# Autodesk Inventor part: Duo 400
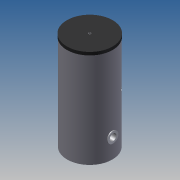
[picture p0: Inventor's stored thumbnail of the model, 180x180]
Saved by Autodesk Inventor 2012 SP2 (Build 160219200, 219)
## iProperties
Created: 2014-05
Part Number: Duo 400
Material: Default
Document SubType Name: Modeling
Designer: michel
Density: 1 g/cm^3
Author: michel
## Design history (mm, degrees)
sketch "Sketch1"
  geometry: C1 r 375 at (0, 0); 1 further point
  constraints: 1 centre point, 1 coincident
  dimensions: "d0" = 750 diameter of C1
extrude "Extrusion1" new body sketch "Sketch1" distance "d1" = 1630; taper "d2" = 0 deg
sketch "Sketch2"
  geometry: L1 (-375, 1630)-(375, 1630) reference; L2 (-375, 0)-(375, 0) reference; L3 (375, 0)-(375, 1630) reference; L4 (375, 1630)-(380, 1630); L5 (380, 1630)-(380, 1580); L6 (380, 1580)-(375, 1580); L7 (375, 1580)-(375, 1630); L8 (0, -326)-(0, 1956) reference; 1 further point
  constraints: 8 end point, 2 parallel, 1 horizontal, 1 perpendicular
  dimensions: "d3" = 5 distance of L5.end L6.end; "d4" = 50 distance of L4.end L5.end
revolve "Revolution1" sketch "Sketch2" stored, may be unused: angle "d5" = 90 deg
workplane "Work Plane1"
workplane "Work Plane2"
workplane "Work Plane3"
workplane "Work Plane4"
workplane "Work Plane5"
workplane "Work Plane6"
sketch "Sketch3"
  geometry: L1 (532, 1470)-(-532, 1470) reference; L2 (532, 870)-(-532, 870) reference; L3 (532, 770)-(-532, 770) reference; L4 (532, 330)-(-532, 330) reference; L5 (532, 70)-(-532, 70) reference; L6 (375, 0)-(375, 1580) reference; L7 (375, 70)-(335, 70); L8 (335, 70)-(335, 86.625); L9 (335, 86.625)-(375, 86.625); L10 (375, 86.625)-(375, 70); L11 (375, 330)-(335, 330); L12 (335, 330)-(335, 346.625); L13 (335, 346.625)-(375, 346.625); L14 (375, 346.625)-(375, 330); L15 (374.76, 770)-(334.76, 770); L16 (334.76, 770)-(334.76, 786.625); L17 (334.76, 786.625)-(374.76, 786.625); L18 (374.76, 786.625)-(374.76, 770); L19 (375, 1470)-(335, 1470); L20 (335, 1470)-(335, 1486.625); L21 (335, 1486.625)-(375, 1486.625); L22 (375, 1486.625)-(375, 1470); L23 (375, 870)-(335, 870); L24 (335, 870)-(335, 883.22); L25 (335, 883.22)-(375, 883.22); L26 (375, 883.22)-(375, 870); 1 further point
  constraints: 40 end point, 10 parallel, 5 horizontal, 5 perpendicular, 2 point on line
  dimensions: "d13" = 40 distance of L8.end L9.end; "d14" = 16.625 distance of L7.end L8.end; "d15" = 40 distance of L12.end L13.end; "d16" = 16.625 distance of L11.end L12.end; "d17" = 40 distance of L16.end L17.end; "d18" = 16.625 distance of L15.end L16.end; "d19" = 40 distance of L20.end L21.end; "d20" = 16.625 distance of L19.end L20.end; "d21" = 40 distance of L24.end L25.end; "d22" = 13.22 distance of L23.end L24.end
revolve "Revolution2" stored, may be unused: angle "d23" = 90 deg
revolve "Revolution3" stored, may be unused: angle "d24" = 90 deg
revolve "Revolution4" stored, may be unused: angle "d25" = 90 deg
revolve "Revolution5" stored, may be unused: angle "d26" = 90 deg
revolve "Revolution6" stored, may be unused: angle "d27" = 90 deg
workplane "Work Plane7"
sketch "Sketch4"
  geometry: C1 r 15.375 at (0, 1470); C2 r 12.25 at (0, 870); C3 r 15.375 at (0, 770); C4 r 15.375 at (0, 330); C5 r 15.375 at (0, 70); 1 further point
  constraints: 5 centre point
  dimensions: "d28" = 30.75 diameter of C1; "d29" = 24.5 diameter of C2; "d30" = 30.75 diameter of C3; "d31" = 30.75 diameter of C4; "d32" = 30.75 diameter of C5
extrude "Extrusion2" cut sketch "Sketch4" distance "d33" = 40; taper "d34" = 0 deg
sketch "Sketch5"
  geometry: L1 (-375, 0)-(-375, 1580) reference; L2 (-375, 0)-(-375, 327); L3 (-249, 327)-(-623, 327); L4 (-375, 327)-(-387.5, 327); L5 (-387.5, 327)-(-387.5, 417); L6 (-387.5, 417)-(-375, 417); L7 (-375, 417)-(-375, 327); 1 further point
  constraints: 12 end point, 2 parallel, 2 perpendicular, 1 horizontal, 1 point on line
  dimensions: "d35" = 327 distance of L1.start L2.end; "d36" = 12.5 distance of L5.end L6.end; "d37" = 90 distance of L4.end L5.end
revolve "Revolution7" sketch "Sketch5" stored, may be unused: angle "d38" = 90 deg
sketch "Sketch6"
  geometry: C1 r 62.5 at (0, 0); A1 r 90 centre (0, 0) between (90, 0) and (-90, 0) reference; 1 further point
  constraints: 1 centre point, 1 coincident
  dimensions: "d39" = 125 diameter of C1
extrude "Extrusion3" join sketch "Sketch6" stored distance "d40" = 40; taper "d41" = 0 deg
sketch "Sketch7"
  geometry: C1 r 90 at (0, 0) reference; C2 r 55 at (0, 0); 1 further point
  constraints: 1 centre point, 1 coincident
  dimensions: "d42" = 110 diameter of C2
extrude "Extrusion4" cut sketch "Sketch7" distance "d43" = 80; taper "d44" = 0 deg
sketch "Sketch8"
  geometry: C1 r 380 at (0, 0) reference; C2 r 20.955 at (0, 0)
  constraints: 1 centre point, 1 coincident
  dimensions: "d45" = 41.91 diameter of C2
extrude "Extrusion5" join sketch "Sketch8" distance "d46" = 2; taper "d47" = 0 deg
sketch "Sketch9"
  geometry: C1 r 20.955 at (0, 0) reference; C2 r 19.625 at (0, 0)
  constraints: 1 centre point, 1 coincident
  dimensions: "d48" = 39.25 diameter of C2
extrude "Extrusion6" cut sketch "Sketch9" distance "d49" = 40; taper "d50" = 0 deg
workplane "Work Plane8"
sketch "Sketch10"
  geometry: L1 (0, 375)-(1580, 375) reference; L2 (870, -742.16)-(870, 748.304) reference; L3 (870, 375)-(893.9, 375); L4 (893.9, 375)-(893.9, 335); L5 (893.9, 335)-(870, 335); L6 (870, 335)-(870, 375); 1 further point
  constraints: 8 end point, 2 parallel, 2 point on line, 1 horizontal, 1 perpendicular
  dimensions: "d52" = 23.9 distance of L4.end L5.end; "d53" = 40 distance of L3.end L4.end
revolve "Revolution8" sketch "Sketch10" stored, may be unused: angle "d54" = 90 deg
sketch "Sketch11"
  geometry: C1 r 22.625 at (0, 0); A1 r 23.9 centre (0, 0) between (23.9, 0) and (-23.9, 0) reference; 1 further point
  constraints: 1 centre point, 1 coincident
  dimensions: "d55" = 45.25 diameter of C1
extrude "Extrusion7" cut sketch "Sketch11" distance "d56" = 40; taper "d57" = 0 deg
sketch "Sketch12"
  geometry: C1 r 22.625 at (0, 0) reference; A1 r 23.9 centre (0, 0) between (-23.9, 0) and (23.9, 0) reference; A2 r 23.9 centre (0, 0) between (23.9, 0) and (-23.9, 0) reference; 1 further point
extrude "Extrusion8" join sketch "Sketch12" distance "d58" = 1; taper "d59" = 0 deg
sketch "Sketch13"
  geometry: C1 r 15.375 at (0, 0) reference; C2 r 15.375 at (260, 0) reference; C3 r 12.25 at (800, 0) reference; C4 r 15.375 at (1400, 0) reference; A1 r 16.625 centre (0, 0) between (16.625, 0) and (-16.625, 0) reference; A2 r 16.625 centre (0, 0) between (-16.625, 0) and (16.625, 0) reference; A3 r 16.625 centre (260, 0) between (276.625, 0) and (243.375, 0) reference; A4 r 16.625 centre (260, 0) between (243.375, 0) and (276.625, 0) reference; A5 r 13.22 centre (800, 0) between (813.22, 0) and (786.78, 0) reference; A6 r 13.22 centre (800, 0) between (786.78, 0) and (813.22, 0) reference; A7 r 16.625 centre (1400, 0) between (1416.625, 0) and (1383.375, 0) reference; A8 r 16.625 centre (1400, 0) between (1383.375, 0) and (1416.625, 0) reference; 1 further point
extrude "Extrusion9" join sketch "Sketch13" distance "d60" = 1; taper "d61" = 0 deg
body "Solid1"
node "Projected Loop1"
node "Projected Loop2"
node "Projected Loop3"
node "Projected Loop4"
other parameters: "d12" = 0, "d51" = 35 deg
